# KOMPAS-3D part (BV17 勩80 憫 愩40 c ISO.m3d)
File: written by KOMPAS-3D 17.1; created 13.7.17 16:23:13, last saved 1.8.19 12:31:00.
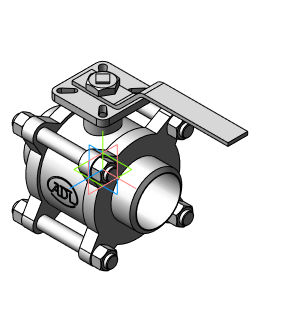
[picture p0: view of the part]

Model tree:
1. Операция без истории:1  (labels: Сталь 20  ГОСТ 1050-88)

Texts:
  DISO1
  DISO2
  BV17 Ду8 1/4" Ру63 с ISO
  BV17 Ду8 СС Ру63 с ISO
  BV17 Ду10 3/8" Ру63 с ISO
  BV17 Ду10 СС Ру63 с ISO
  BV17 Ду15 1/2" Ру63 с ISO
  BV17 Ду15 СС Ру63 с ISO
  BV17 Ду15 ФФ Ру40 с ISO
  BV17 Ду20 3/4" Ру63 с ISO
  BV17 Ду20 СС Ру40 с ISO
  BV17 Ду20 ФФ Ру40 с ISO
  BV17 Ду25 1" Ру63 с ISO
  BV17 Ду25 СС Ру63 с ISO
  BV17 Ду25 ФФ Ру40 с ISO
  BV17 Ду32 1 1/4" Ру63 с ISO
  BV17 Ду32 СС Ру63 с ISO
  BV17 Ду32 ФФ Ру40 с ISO
  BV17 Ду40 1 1/2" Ру63 с ISO
  BV17 Ду40 СС Ру63 с ISO
  BV17 Ду40 ФФ Ру40 с ISO
  BV17 Ду50 2" Ру63 с ISO
  BV17 Ду50 СС Ру63 с ISO
  BV17 Ду50 ФФ Ру40 с ISO
  BV17 Ду65 2 1/2" Ру40 с ISO
  BV17 Ду65 СС Ру40 с ISO
  BV17 Ду65 ФФ Ру40 с ISO
  BV17 Ду80 3" Ру40 с ISO
  BV17 Ду80 СС Ру40 с ISO
  BV17 Ду80 ФФ Ру40 с ISO
  BV17 Ду100 4" Ру40 с ISO
  BV17 Ду100 СС Ру40 с ISO
  BV17 Ду100 ФФ Ру40 с ISO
